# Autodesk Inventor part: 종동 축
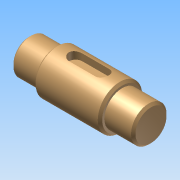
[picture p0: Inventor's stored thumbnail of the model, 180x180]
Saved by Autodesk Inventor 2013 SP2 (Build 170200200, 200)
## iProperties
Created: 2026-10
Part Number: 종동 축
Material: Generic
Document SubType Name: Modeling
Designer: a
Density: 1 g/cm^3
Author: a
변환 표준: STEP AP214IS
전처리기: Build: 200, Release: 2013 SP2 Update 6 - Date: Thu 07/17/2014
전송 단위: 밀리미터
불확실성: 0.01
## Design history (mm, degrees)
node "종동 축1"
node "솔리드1"
node "기준1"
